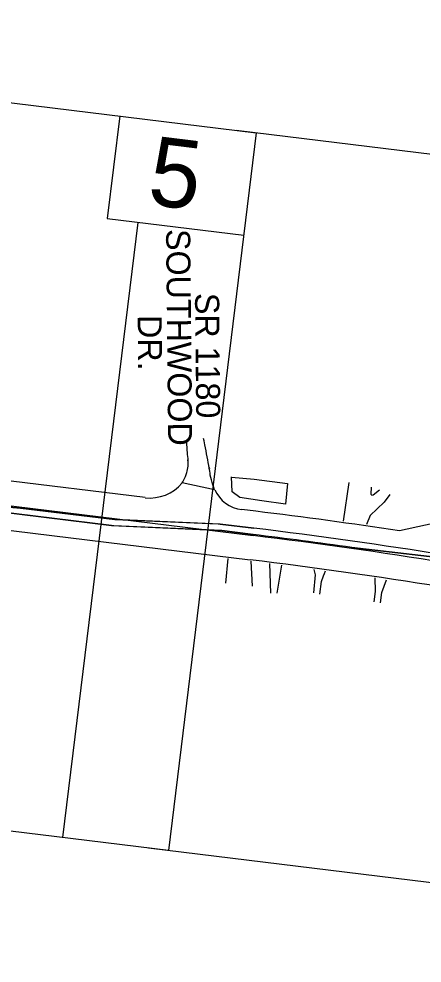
# Model space of a CAD drawing. Extents: x 1756435 to 1766932, y 416863 to 426859.
# Drawn here: x 1763823 to 1764409, y 423056 to 424427 of the extents above; entities that cross this region are included whole.
import ezdxf

# ---------------------------------------------------------------- set-up
doc = ezdxf.new("R2010")
doc.units = 0
for name, color, linetype in [('Exist Roads EOP', 7, 'Continuous'), ('Exist Roads EOP Other', 7, 'Continuous'), ('Exist Roads Soil', 7, 'Continuous'), ('Prop Horizontal Alignment', 7, 'Continuous'), ('Prop Shade Light', 7, 'Continuous'), ('Prop Shade Medium', 7, 'Continuous'), ('Sheet Data Field CELL', 7, 'Continuous'), ('Sheet Plan CELL', 7, 'Continuous')]:
    doc.layers.add(name, color=color, linetype=linetype)

msp = doc.modelspace()

# ---------------------------------------------------------------- linework, layer by layer
at = {"layer": 'Exist Roads EOP'}
for points in [[(1764069.1, 423785.8), (1764069, 423788.4), (1764068.7, 423791.3), (1764068.5, 423794.3), (1764068.2, 423797), (1764068, 423800.2), (1764067.7, 423804.3), (1764067.4, 423808.8), (1764067.1, 423813), (1764067, 423813.9)], [(1764099.8, 423774.7), (1764099.1, 423778.3), (1764098.4, 423782.3), (1764097.7, 423786.5), (1764096.9, 423790.8), (1764096.1, 423795), (1764095.3, 423799.4), (1764094.4, 423803.8), (1764093.6, 423808), (1764092.4, 423813.7), (1764091.7, 423817.4)], [(1764060.3, 423752.9), (1764061.4, 423754.4), (1764062.5, 423756.3), (1764063.5, 423758.1), (1764064.4, 423760.1), (1764065.3, 423762.3), (1764066.3, 423765), (1764067.2, 423767.7), (1764067.9, 423770), (1764068.3, 423772.1), (1764068.7, 423774.5), (1764069, 423777), (1764069.1, 423779.8), (1764069.2, 423782.7), (1764069.1, 423785.4), (1764067.8, 423785.4)], [(1764107.7, 423743), (1764106.4, 423746.3), (1764105, 423750.1), (1764103.9, 423753.6), (1764103, 423757.1), (1764102.1, 423760.8), (1764101.4, 423764.2), (1764101, 423766.8), (1764100.6, 423769.9), (1764099.8, 423774.4), (1764101.1, 423774.6)]]:
    msp.add_lwpolyline(points, dxfattribs=at)
at = {"layer": 'Exist Roads EOP Other'}
for p, q in [((1764126.7, 423643.2), (1764123.4, 423607.1)), ((1764162.6, 423602.8), (1764160.8, 423639)), ((1764187.5, 423635.7), (1764188.9, 423592.5)), ((1764198.8, 423592.6), (1764205.5, 423633.4))]:
    msp.add_line(p, q, dxfattribs=at)
for points in [[(1764132.2, 423761.3), (1764165.1, 423758.2), (1764213.4, 423752), (1764210.6, 423721.9), (1764176.5, 423726.9), (1764144.1, 423731.7), (1764133.3, 423739.7), (1764132.1, 423761.7)], [(1764252, 423627.2), (1764253.7, 423619.5), (1764251.6, 423593.4)], [(1764260.7, 423591.5), (1764263.2, 423609.9), (1764265.8, 423617.8), (1764265.9, 423617.8), (1764265.9, 423617.8), (1764267.3, 423621.2), (1764268.9, 423625)], [(1764340.5, 423614.8), (1764341, 423595.2), (1764339.1, 423580.3)], [(1764348.8, 423578.8), (1764350.7, 423593.9), (1764357.4, 423612.3)]]:
    msp.add_lwpolyline(points, dxfattribs=at)
at = {"layer": 'Exist Roads Soil'}
msp.add_line((1764294.9, 423697.1), (1764303.1, 423753.6), dxfattribs=at)
for points in [[(1764335, 423746.5), (1764334.6, 423736.4), (1764336.4, 423734.8), (1764338.3, 423735.6), (1764347.3, 423742.7)], [(1764362.4, 423736.2), (1764354.2, 423724.8), (1764333.7, 423705.4), (1764328.2, 423692.3)]]:
    msp.add_lwpolyline(points, dxfattribs=at)
at = {"layer": 'Prop Horizontal Alignment'}
msp.add_line((1763550.1, 423751.5), (1764163.5, 423676.4), dxfattribs=at)
msp.add_arc((1763235.6, 416093.6), 7639.4, 80.91031, 83.0234, dxfattribs=at)
at = {"layer": 'Prop Shade Light'}
for p, q in [((1764006.8, 423731.4), (1763622.9, 423778.4)), ((1764107.7, 423743), (1764060.4, 423752.9)), ((1763958, 423690.8), (1763624.5, 423731.6)), ((1763673.2, 423729.6), (1763825.4, 423716.3)), ((1763825.4, 423716.3), (1763962.4, 423699.5)), ((1764167.8, 423711.7), (1764147.1, 423714.2)), ((1764513, 423713.5), (1764376.3, 423683.3)), ((1763705.6, 423696.7), (1764159.2, 423641.2)), ((1764115.9, 423693.1), (1764164.8, 423687.1)), ((1764163.6, 423677.9), (1764118, 423683.5)), ((1764460.1, 423641.1), (1764307, 423659))]:
    msp.add_line(p, q, dxfattribs=at)
for points in [[(1763962.4, 423699.5), (1764112.7, 423693.2), (1764115.9, 423693.1)], [(1764118, 423683.5), (1763961.2, 423690.6), (1763958, 423690.8)]]:
    msp.add_lwpolyline(points, dxfattribs=at)
for centre, radius, start, end in [((1764014, 423790.9), 60, 263.0234, 320.5856), ((1764153.2, 423763.8), 50, 204.6812, 263.0234), ((1763235.6, 416093.6), 7674.9, 81.45201, 83.0234), ((1763235.6, 416093.6), 7650.2, 80.91031, 83.0234), ((1763235.6, 416093.6), 7640.9, 81.93916, 83.0234), ((1763235.6, 416093.6), 7603.9, 80.91031, 83.0234)]:
    msp.add_arc(centre, radius, start, end, dxfattribs=at)
at = {"layer": 'Prop Shade Medium'}
for p, q in [((1763624.5, 423731.6), (1763958, 423690.8)), ((1763825.4, 423716.3), (1763673.2, 423729.6)), ((1763962.4, 423699.5), (1763825.4, 423716.3)), ((1764115.9, 423693.1), (1763962.4, 423699.5)), ((1763958, 423690.8), (1764118, 423683.5)), ((1764164.8, 423687.1), (1764115.9, 423693.1)), ((1764118, 423683.5), (1764163.6, 423677.9)), ((1764307, 423659), (1764460.1, 423641.1))]:
    msp.add_line(p, q, dxfattribs=at)
for radius, start in [(7650.2, 80.91031), (7640.9, 81.93916)]:
    msp.add_arc((1763235.6, 416093.6), radius, start, 83.0234, dxfattribs=at)
at = {"layer": 'Sheet Plan CELL'}
for p, q in [((1763969.7, 424285.6), (1763951.5, 424136.6)), ((1763951.5, 424136.6), (1764150.1, 424112.3))]:
    msp.add_line(p, q, dxfattribs=at)
for points in [[(1762817.9, 424426.5), (1764168.3, 424261.3), (1764040.8, 423219), (1762690.4, 423384.3)], [(1764139.1, 424264.8), (1765503.7, 424097.9), (1765376.2, 423055.6), (1764011.6, 423222.6)], [(1763887.2, 423237.8), (1763996.5, 424131.1)]]:
    msp.add_lwpolyline(points, dxfattribs=at)

# ---------------------------------------------------------------- texts
at = {"layer": 'Sheet Data Field CELL'}
for s, p in [('SOUTHWOOD', (1764037.1, 424121.2)), ('SR 1180', (1764079.2, 424028.5)), ('DR.', (1763995.8, 423996.3))]:
    msp.add_text(s, height=35, rotation=270.5562, dxfattribs=at).set_placement(p)
at = {"layer": 'Sheet Plan CELL'}
msp.add_text('5', height=100, rotation=353.0234, dxfattribs=at).set_placement((1764008.2, 424157.6))

doc.saveas('drawing.dxf')
